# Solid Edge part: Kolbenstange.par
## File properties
Username: bmolnar
Dokumentum tartalom típus: 0
Author: bmolnar
Last saved by: bmolnar
Revision: 91
Sűrűség: 0,000 kg/m^3
Pontosság: 0,990
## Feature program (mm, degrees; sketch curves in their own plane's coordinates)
base feature "unnamed BaseFeature 1"
sketch for "unnamed Protrusion 1" plane through (29, 0, 0) normal (1, 0, 0) x-axis (0, -1, 0)
  circle centre (0, 0) radius 40
extrude "unnamed Protrusion 1" add finite 12 along +normal
thread "unnamed Thread 1"
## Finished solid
Body 1: solid body, 13 faces, 19 edges, 8 vertices.
  Faces by surface: plane 7, cylinder 3, cone 2, torus 1
  Edges by curve: circle 9, line 6, ellipse 2, intersection 2
Bounding box of the edges (mm; curved faces can reach further): 161.000 x 80.000 x 80.000, from (-120, -40, -40) to (41, 40, 40).
Cylindrical faces by radius (mm): R5.053 x1, R10 x1, R40 x1
Conical faces (half-angle, radius in mm at the cone's reference point): 45 deg R5.553 x1, 59 deg R2.5265 x1
Toroidal faces (ring radius, tube radius in mm): R8.2 r1.8 x1
Planar faces by outward normal: +x 1, +z 1, -x 2, -z 1, oblique 2
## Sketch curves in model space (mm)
circle centre (29, 0, 0) radius 40
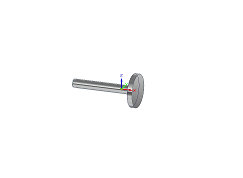
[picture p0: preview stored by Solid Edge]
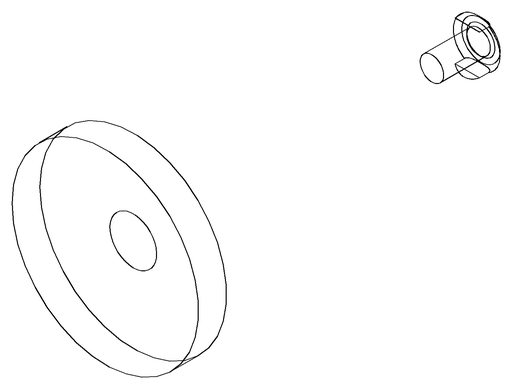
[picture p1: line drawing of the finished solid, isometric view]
